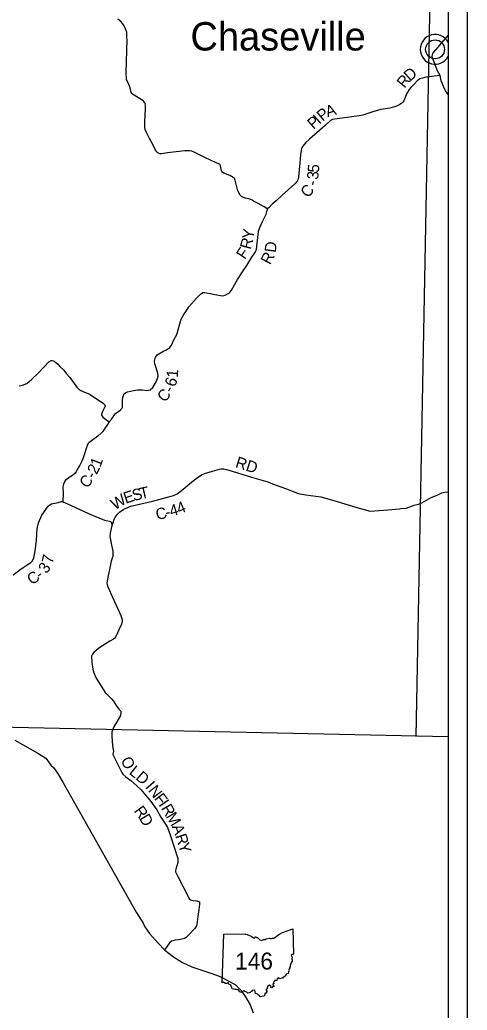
# Model space of a CAD drawing. Extents: x -452339 to 6403467, y -1 to 1814750.
# Drawn here: x -44654 to -32848, y 1614709 to 1640875 of the extents above; entities that cross this region are included whole.
import ezdxf

# ---------------------------------------------------------------- set-up
doc = ezdxf.new("R2010")
doc.units = 0
for name, color, linetype in [('Default', 7, 'Continuous'), ('GM_X_Adjacent_County_Text', 7, 'Continuous'), ('GM_X_County', 7, 'Continuous'), ('GM_X_County_Road', 7, 'Continuous'), ('GM_X_County_Road_Text', 7, 'Continuous'), ('GM_X_Section', 7, 'Continuous'), ('GM_X_Section_Text', 7, 'Continuous')]:
    doc.layers.add(name, color=color, linetype=linetype)

msp = doc.modelspace()

# ---------------------------------------------------------------- linework, layer by layer
at = {"layer": 'Default'}
for p, q in [((-33348, 1655312), (-33348, 1597935)), ((-39313, 1615429), (-39271, 1616720))]:
    msp.add_line(p, q, dxfattribs=at)
msp.add_lwpolyline([(-91226, 1655812), (-32848, 1655812), (-32848, 1597435), (-91226, 1597435)], close=True, dxfattribs=at)
for points in [[(-33557, 1639408), (-33717, 1639387), (-33842, 1639366), (-33930, 1639356), (-34026, 1639337), (-34101, 1639312), (-34166, 1639260), (-34249, 1639178), (-34333, 1639089), (-34379, 1639034), (-34418, 1638974), (-34449, 1638916), (-34488, 1638819), (-34523, 1638739), (-34544, 1638703), (-34572, 1638670), (-34649, 1638622), (-34766, 1638574), (-34892, 1638545), (-35061, 1638516), (-35131, 1638502), (-35215, 1638479), (-35308, 1638457), (-35549, 1638374), (-35601, 1638358), (-35698, 1638339), (-36145, 1638281), (-36347, 1638252), (-36400, 1638240), (-36454, 1638211), (-36596, 1638087), (-37011, 1637721), (-37108, 1637632), (-37186, 1637535), (-37216, 1637477), (-37231, 1637419), (-37249, 1637305), (-37263, 1637093), (-37298, 1636723), (-37307, 1636665), (-37334, 1636613), (-37397, 1636544), (-37729, 1636238), (-37891, 1636094), (-37998, 1636001), (-38080, 1635910), (-38111, 1635888), (-38135, 1635893), (-38202, 1635931), (-38366, 1636024), (-38484, 1636083), (-38523, 1636114), (-38581, 1636136), (-38695, 1636162), (-38766, 1636189), (-38806, 1636207), (-38840, 1636242), (-38902, 1636361), (-38969, 1636642), (-38992, 1636691), (-39020, 1636713), (-39115, 1636766), (-39267, 1636823), (-39306, 1636847), (-39332, 1636885), (-39351, 1636970), (-39356, 1637016), (-39368, 1637040), (-39382, 1637058), (-39416, 1637079), (-39471, 1637096), (-39768, 1637240), (-40050, 1637378), (-40112, 1637402), (-40178, 1637417), (-40302, 1637413), (-40753, 1637359), (-40918, 1637335), (-40958, 1637337), (-41009, 1637360), (-41035, 1637388), (-41069, 1637429), (-41145, 1637582), (-41229, 1637737), (-41299, 1637879), (-41342, 1637973), (-41353, 1638038), (-41355, 1638192), (-41341, 1638526), (-41337, 1638616), (-41347, 1638653), (-41359, 1638681), (-41386, 1638723), (-41450, 1638766), (-41640, 1638881), (-41680, 1638907), (-41700, 1638928), (-41713, 1638954), (-41746, 1639080), (-41771, 1639147), (-41804, 1639229), (-41835, 1639288), (-41843, 1639314), (-41849, 1639471), (-41825, 1640352), (-41826, 1640392), (-41828, 1640464), (-41831, 1640550), (-41848, 1640593), (-41870, 1640651), (-41901, 1640715), (-41938, 1640772), (-41991, 1640827), (-42069, 1640888)], [(-41905, 1630983), (-41904, 1630984), (-41900, 1630994), (-41868, 1631016), (-41814, 1631047), (-41650, 1631082), (-41546, 1631103), (-41414, 1631102), (-41306, 1631080), (-41218, 1631103), (-41146, 1631162), (-41053, 1631312), (-41019, 1631397), (-41004, 1631461), (-41016, 1631537), (-41088, 1631787), (-41097, 1631859), (-41076, 1631960), (-41028, 1632020), (-40876, 1632115), (-40785, 1632156), (-40695, 1632221), (-40649, 1632279), (-40590, 1632418), (-40511, 1632563), (-40396, 1632964), (-40317, 1633103), (-40265, 1633175), (-40190, 1633290), (-39995, 1633524), (-39882, 1633627), (-39824, 1633667), (-39774, 1633674), (-39587, 1633637), (-39458, 1633612), (-39305, 1633581), (-39231, 1633598), (-39177, 1633632), (-39117, 1633658), (-39065, 1633733), (-38909, 1634017), (-38778, 1634214), (-38667, 1634387), (-38529, 1634602), (-38432, 1634747), (-38408, 1634814), (-38361, 1635203), (-38351, 1635289), (-38316, 1635387), (-38249, 1635546), (-38156, 1635741), (-38131, 1635813), (-38111, 1635888)], [(-44671, 1631206), (-44581, 1631221), (-44472, 1631266), (-44348, 1631370), (-44161, 1631551), (-43886, 1631835), (-43828, 1631870), (-43798, 1631872), (-43746, 1631859), (-43663, 1631787), (-43600, 1631719), (-43489, 1631616), (-43418, 1631526), (-43335, 1631429), (-43147, 1631168), (-43100, 1631120), (-43046, 1631084), (-42903, 1631023), (-42853, 1631001), (-42795, 1630972), (-42443, 1630736), (-42412, 1630704), (-42404, 1630680), (-42408, 1630654), (-42473, 1630523), (-42501, 1630449), (-42497, 1630427), (-42464, 1630381), (-42462, 1630379)], [(-42293, 1630252), (-42228, 1630332), (-42152, 1630439), (-42116, 1630479), (-42047, 1630526), (-41993, 1630568), (-41963, 1630603), (-41947, 1630643), (-41941, 1630833), (-41933, 1630898), (-41920, 1630950), (-41905, 1630983)], [(-42462, 1630379), (-42460, 1630378), (-42293, 1630252), (-42341, 1630181), (-42418, 1630065), (-42465, 1629994), (-42495, 1629960), (-42597, 1629871), (-42764, 1629748), (-42836, 1629697), (-42852, 1629681), (-42872, 1629651), (-42901, 1629548), (-42950, 1629412), (-42995, 1629275), (-43019, 1629217), (-43072, 1629108), (-43129, 1629012), (-43171, 1628933), (-43195, 1628901), (-43266, 1628836), (-43350, 1628784), (-43408, 1628743), (-43450, 1628713), (-43477, 1628664), (-43503, 1628610), (-43515, 1628538), (-43513, 1628364), (-43520, 1628151), (-43492, 1628135), (-43295, 1628045), (-42826, 1627827), (-42573, 1627713), (-42415, 1627658), (-42290, 1627629), (-42256, 1627621), (-42217, 1627535), (-42233, 1627479), (-42270, 1627310), (-42277, 1627228), (-42271, 1627180), (-42234, 1626994), (-42200, 1626838), (-42198, 1626786), (-42203, 1626706), (-42239, 1626571), (-42347, 1626049), (-42358, 1625989), (-42340, 1625919), (-42265, 1625739), (-41992, 1625136), (-41959, 1625060), (-41953, 1625028), (-41955, 1624988), (-41974, 1624908), (-42035, 1624779), (-42120, 1624584), (-42148, 1624542), (-42184, 1624510), (-42275, 1624459), (-42566, 1624271), (-42702, 1624157), (-42738, 1624113), (-42759, 1624061), (-42756, 1623894), (-42731, 1623722), (-42704, 1623622), (-42637, 1623478), (-42511, 1623269), (-42402, 1623103), (-42237, 1622939), (-42178, 1622875), (-42113, 1622761), (-42044, 1622659), (-41984, 1622607), (-41984, 1622552), (-42006, 1622478), (-42169, 1622191), (-42207, 1622104), (-42223, 1622055), (-42223, 1622039)], [(-42217, 1627535), (-42192, 1627597), (-42162, 1627680), (-42131, 1627742), (-42077, 1627817), (-42024, 1627871), (-41912, 1627942), (-41722, 1628022), (-41498, 1628079), (-41156, 1628156), (-40950, 1628211), (-40657, 1628286), (-40599, 1628304), (-40503, 1628347), (-40427, 1628401), (-40294, 1628518), (-40124, 1628656), (-39973, 1628775), (-39859, 1628854), (-39784, 1628885), (-39570, 1628946), (-39446, 1628985), (-39382, 1629002), (-39336, 1629010), (-39270, 1629011), (-39167, 1628989), (-38537, 1628795), (-38113, 1628664), (-37985, 1628613), (-37770, 1628538), (-37613, 1628485), (-37483, 1628432), (-37326, 1628371), (-37266, 1628351), (-37108, 1628326), (-36711, 1628269), (-36363, 1628171), (-35697, 1627976), (-35474, 1627909), (-35420, 1627897), (-35292, 1627898), (-34940, 1627931), (-34637, 1627958), (-34597, 1627962)], [(-34597, 1627962), (-34459, 1627974), (-34243, 1628054), (-34134, 1628075), (-34042, 1628112), (-33798, 1628251), (-33637, 1628315), (-33516, 1628375), (-33440, 1628397), (-33348, 1628400)], [(-42223, 1622039), (-42222, 1621965), (-42214, 1621796), (-42200, 1621635), (-42179, 1621552), (-42200, 1621460), (-42063, 1621184), (-41964, 1620986), (-41933, 1620942), (-41853, 1620875), (-41726, 1620773), (-41567, 1620640), (-41456, 1620529), (-41337, 1620393), (-41223, 1620254), (-41041, 1620003), (-40930, 1619807), (-40865, 1619703), (-40808, 1619626), (-40760, 1619538), (-40684, 1619342), (-40487, 1618714), (-40481, 1618672), (-40484, 1618610), (-40537, 1618435), (-40547, 1618397), (-40547, 1618367), (-40484, 1618241), (-40195, 1617675)], [(-40195, 1617675), (-40193, 1617672), (-40191, 1617668), (-40173, 1617640), (-40151, 1617626), (-40089, 1617610), (-39986, 1617601), (-39970, 1617597), (-39942, 1617581), (-39914, 1617569), (-39916, 1617509), (-39932, 1617365), (-39957, 1617180), (-39984, 1616973), (-39991, 1616941), (-40037, 1616871), (-40224, 1616669), (-40266, 1616629), (-40307, 1616604), (-40375, 1616582), (-40467, 1616571), (-40553, 1616556), (-40613, 1616542), (-40653, 1616530), (-40693, 1616493), (-40832, 1616301)], [(-39271, 1616720), (-38699, 1616728), (-38708, 1616713), (-38654, 1616709), (-38597, 1616682), (-38548, 1616665), (-38489, 1616624), (-38453, 1616624), (-38438, 1616658), (-38411, 1616632), (-38379, 1616627), (-38323, 1616565), (-38277, 1616552), (-38221, 1616573), (-38181, 1616576), (-38150, 1616597), (-38072, 1616615), (-38050, 1616604), (-38008, 1616607), (-37987, 1616615), (-37951, 1616608), (-37887, 1616655), (-37822, 1616710), (-37720, 1616762), (-37570, 1616811), (-37450, 1616856), (-37433, 1616186)], [(-37433, 1616186), (-37450, 1616176), (-37478, 1616181), (-37496, 1616162), (-37473, 1616131), (-37463, 1616097), (-37472, 1616061), (-37463, 1616031), (-37469, 1616006), (-37486, 1615980), (-37492, 1615957), (-37507, 1615931), (-37506, 1615917), (-37520, 1615907), (-37517, 1615864), (-37524, 1615841), (-37522, 1615821), (-37545, 1615816), (-37539, 1615799), (-37554, 1615786), (-37551, 1615765), (-37567, 1615750), (-37551, 1615722), (-37564, 1615713), (-37575, 1615679), (-37604, 1615672), (-37661, 1615610), (-37682, 1615586), (-37705, 1615580), (-37718, 1615556), (-37746, 1615556), (-37790, 1615539), (-37817, 1615568), (-37866, 1615533), (-37872, 1615493), (-37933, 1615494), (-37931, 1615474), (-37944, 1615468), (-37957, 1615448), (-37950, 1615411), (-37979, 1615402), (-37975, 1615381), (-37956, 1615368), (-37948, 1615328), (-37979, 1615336), (-38004, 1615302), (-38030, 1615310), (-38022, 1615339), (-38065, 1615374), (-38106, 1615346), (-38128, 1615302), (-38128, 1615272), (-38159, 1615254), (-38139, 1615212), (-38143, 1615183), (-38142, 1615155), (-38181, 1615157), (-38204, 1615082)], [(-38204, 1615082), (-38271, 1615068), (-38317, 1615060), (-38333, 1615093), (-38367, 1615111), (-38388, 1615145), (-38436, 1615149), (-38447, 1615196), (-38452, 1615234), (-38518, 1615225), (-38535, 1615202), (-38558, 1615195), (-38572, 1615172), (-38603, 1615170), (-38637, 1615159), (-38659, 1615182), (-38715, 1615205), (-38740, 1615217), (-38792, 1615198), (-38803, 1615177), (-38844, 1615186), (-38854, 1615210), (-38879, 1615218), (-38884, 1615243), (-38938, 1615257), (-38979, 1615252), (-39051, 1615272), (-39056, 1615306), (-39080, 1615348), (-39093, 1615376), (-39138, 1615398), (-39148, 1615432), (-39162, 1615431), (-39176, 1615417), (-39227, 1615411), (-39247, 1615425), (-39275, 1615449), (-39313, 1615429)]]:
    msp.add_lwpolyline(points, dxfattribs=at)
at = {"layer": 'GM_X_County_Road'}
for points in [[(-33348, 1638901), (-33417, 1638997), (-33466, 1639096), (-33532, 1639261), (-33557, 1639408), (-33628, 1639523), (-33764, 1639873), (-33771, 1639918), (-33751, 1639985), (-33728, 1640019), (-33617, 1640149), (-33533, 1640247), (-33348, 1640457)], [(-44782, 1621844), (-44177, 1621499), (-43970, 1621365), (-43835, 1621186), (-43761, 1621125), (-43658, 1620973), (-43515, 1620735), (-41580, 1617301), (-41486, 1617153), (-41396, 1617006), (-41359, 1616910), (-41233, 1616734), (-40999, 1616480), (-40832, 1616301), (-40826, 1616294), (-40601, 1616121), (-40427, 1616012), (-40363, 1615972), (-40115, 1615856), (-39617, 1615685), (-39369, 1615595), (-39155, 1615488), (-38967, 1615386), (-38819, 1615242), (-38702, 1615063), (-38576, 1614850), (-38499, 1614637)]]:
    msp.add_lwpolyline(points, dxfattribs=at)
at = {"layer": 'GM_X_County_Road_Text'}
msp.add_circle((-33695, 1640095), 249, dxfattribs=at)
msp.add_arc((-33695, 1640095), 393, 27.9792, 332.0208, dxfattribs=at)
at = {"layer": 'GM_X_Section'}
msp.add_lwpolyline([(-44827, 1626210), (-44657, 1626340), (-44564, 1626407), (-44461, 1626475), (-44366, 1626535), (-44325, 1626576), (-44284, 1626651), (-44246, 1626848), (-44218, 1627114), (-44192, 1627431), (-44160, 1627582), (-44072, 1627788), (-43910, 1628025), (-43866, 1628060), (-43819, 1628087), (-43642, 1628124), (-43558, 1628149), (-43520, 1628151)], dxfattribs=at)
at = {"layer": 'GM_X_Section_Text'}
for p, q in [((-34196, 1621943), (-33790, 1643152)), ((-66133, 1622641), (-33348, 1621942))]:
    msp.add_line(p, q, dxfattribs=at)

# ---------------------------------------------------------------- texts
at = {"layer": 'Default'}
msp.add_text('146', height=447.7, dxfattribs=at).set_placement((-38973, 1615783))
at = {"layer": 'GM_X_Adjacent_County_Text'}
msp.add_text('Chaseville', height=750, rotation=0, dxfattribs=at).set_placement((-40151, 1640064))
at = {"layer": 'GM_X_County'}
for s, rotation, p in [('R', 50.7251, (-34503, 1639051)), ('D', 42.0803, (-34356, 1639233)), ('A', 18.0444, (-36534, 1638296)), ('P', 41.4094, (-36906, 1637966)), ('I', 41.3438, (-36754, 1638100)), ('P', 40.0246, (-36663, 1638180)), ('5', 84.8487, (-36764, 1636827)), ('3', 84.8445, (-36780, 1636643)), ('C', 49.2539, (-37051, 1636152)), ('-', 75.0151, (-36822, 1636468)), ('Y', 82.1193, (-38492, 1635066)), ('R', 75.4588, (-38561, 1634791)), ('D', 82.6809, (-37902, 1634712)), ('F', 56.555, (-38716, 1634525)), ('R', 62.1188, (-38052, 1634385)), ('1', 86.1289, (-40486, 1631412)), ('6', 73.1837, (-40552, 1631162)), ('C', 50.4338, (-40828, 1630750)), ('-', 61.9541, (-40635, 1630994)), ('2', 63.873, (-42625, 1628843)), ('1', 69.6432, (-42530, 1629039)), ('RD', 342.4992, (-38986, 1629058)), ('-', 62.5198, (-42685, 1628727)), ('C', 49.3923, (-42887, 1628478)), ('W', 30.5301, (-42144, 1627917)), ('E', 18.874, (-41859, 1628087)), ('S', 14.1999, (-41653, 1628158)), ('T', 12.7566, (-41459, 1628207)), ('4', 22.0714, (-40448, 1627809)), ('C', 14.4215, (-41025, 1627652)), ('-', 14.7411, (-40785, 1627714)), ('4', 15.9741, (-40659, 1627747)), ('3', 54.5647, (-43949, 1626222)), ('7', 77.0313, (-43790, 1626489)), ('C', 33.6608, (-44339, 1625931)), ('-', 35.8265, (-44124, 1626074)), ('O', 295.5501, (-41998, 1621320)), ('L', 321.8164, (-41791, 1620965)), ('D', 318.9416, (-41617, 1620829)), ('I', 311.3269, (-41361, 1620597)), ('N', 307.8076, (-41283, 1620509)), ('F', 306.8214, (-41122, 1620301)), ('I', 304.7401, (-41002, 1620141)), ('R', 305.6606, (-41656, 1619974)), ('R', 300.1665, (-40935, 1620046)), ('D', 301.1705, (-41516, 1619779)), ('M', 301.1074, (-40809, 1619828)), ('A', 290.1723, (-40647, 1619563)), ('R', 287.6462, (-40557, 1619318)), ('Y', 287.3682, (-40482, 1619084))]:
    msp.add_text(s, height=300, rotation=rotation, dxfattribs=at).set_placement(p)

doc.saveas('drawing.dxf')
